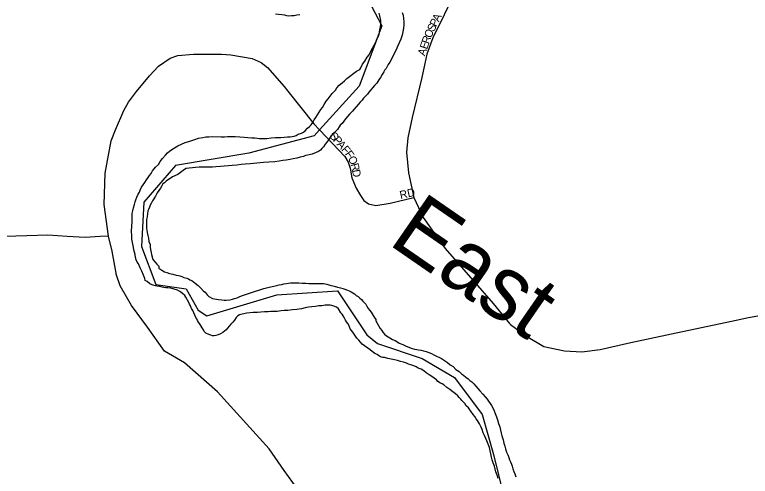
# Model space of a CAD drawing. Extents: x -561 to 1170, y 0 to 846.
# Drawn here: x 98.65 to 111.07, y 180.55 to 188.34 of the extents above; entities that cross this region are included whole.
import ezdxf

# ---------------------------------------------------------------- set-up
doc = ezdxf.new("R2010")
doc.units = 0
for name, color, linetype in [('GM_X_City_Street', 7, 'Continuous'), ('GM_X_City_Street_Text', 7, 'Continuous'), ('GM_X_County_Road', 7, 'Continuous'), ('GM_X_Major_River', 7, 'Continuous'), ('GM_X_Major_River_Text', 7, 'Continuous'), ('GM_X_Township', 7, 'Continuous')]:
    doc.layers.add(name, color=color, linetype=linetype)

msp = doc.modelspace()

# ---------------------------------------------------------------- linework, layer by layer
at = {"layer": 'GM_X_City_Street'}
for points in [[(106.097, 188.748), (105.711, 187.954), (105.606, 187.677), (105.524, 187.28), (105.36, 186.607), (105.285, 186.263), (105.262, 186.024), (105.3, 185.672), (105.387, 185.256), (105.547, 184.919), (105.916, 184.398), (106.384, 183.864), (106.727, 183.468), (107.002, 183.131)], [(103.909, 186.282), (103.921, 186.269), (104.223, 185.951), (104.278, 185.853), (104.316, 185.751), (104.341, 185.59), (104.414, 185.416), (104.486, 185.293), (104.545, 185.208), (104.626, 185.148), (104.745, 185.123), (104.991, 185.161), (105.387, 185.256)], [(107.002, 183.131), (107.017, 183.112), (107.287, 182.914), (107.584, 182.743), (107.933, 182.67), (108.223, 182.65), (108.533, 182.69), (109.047, 182.809), (109.734, 182.954), (110.749, 183.17), (111.035, 183.23), (111.351, 183.288)]]:
    msp.add_lwpolyline(points, dxfattribs=at)
at = {"layer": 'GM_X_County_Road'}
for points in [[(100.237, 184.604), (100.161, 185.137), (100.18, 185.669), (100.283, 186.213), (100.356, 186.401), (100.495, 186.727), (100.573, 186.866), (100.708, 187.049), (100.928, 187.309), (101.08, 187.476), (101.279, 187.609), (101.406, 187.654), (101.669, 187.675), (102.144, 187.678), (102.298, 187.666), (102.66, 187.606), (102.812, 187.533), (102.92, 187.454), (103.202, 187.129), (103.263, 187.051)], [(103.263, 187.051), (103.7, 186.503), (103.799, 186.398), (103.909, 186.282)], [(103.421, 180.343), (103.201, 180.649), (102.948, 181.016), (102.076, 181.979), (101.519, 182.465), (101.181, 182.664), (100.893, 183.07), (100.627, 183.433), (100.433, 183.763), (100.368, 183.962), (100.365, 183.98), (100.297, 184.349), (100.237, 184.604), (100.098, 184.6), (99.844, 184.584), (99.541, 184.6), (99.211, 184.62), (98.861, 184.612), (97.37, 184.564), (96.936, 184.564), (96.144, 184.537)]]:
    msp.add_lwpolyline(points, dxfattribs=at)
at = {"layer": 'GM_X_Major_River'}
for points in [[(105.193, 188.381), (105.209, 188.332), (105.215, 188.278), (105.22, 188.224), (105.221, 188.169), (105.215, 188.115), (105.205, 188.056), (105.189, 187.996), (105.167, 187.931), (105.14, 187.866), (105.113, 187.806), (105.092, 187.752), (105.049, 187.676), (105.017, 187.605), (104.984, 187.54), (104.957, 187.502), (104.936, 187.47), (104.92, 187.437), (104.898, 187.41), (104.882, 187.377), (104.855, 187.334), (104.828, 187.285), (104.796, 187.242), (104.763, 187.187), (104.726, 187.149), (104.628, 187.035), (104.607, 187.003), (104.575, 186.965), (104.542, 186.932), (104.515, 186.899), (104.483, 186.867), (104.45, 186.829), (104.413, 186.785), (104.375, 186.742), (104.353, 186.715), (104.305, 186.666), (104.267, 186.622), (104.235, 186.584), (104.208, 186.546), (104.181, 186.508), (104.148, 186.476), (104.127, 186.449), (104.1, 186.405), (104.051, 186.356), (104.013, 186.318), (103.981, 186.28), (103.949, 186.231), (103.922, 186.193), (103.895, 186.155), (103.862, 186.112), (103.835, 186.085), (103.814, 186.057), (103.781, 186.036), (103.673, 185.987), (103.597, 185.97), (103.559, 185.965), (103.527, 185.948), (103.473, 185.937), (103.413, 185.921), (103.354, 185.91), (103.3, 185.899), (103.235, 185.888), (103.18, 185.882), (103.115, 185.871), (103.045, 185.86), (102.942, 185.854), (102.85, 185.849), (102.742, 185.837), (102.628, 185.826), (102.541, 185.82), (102.476, 185.815), (102.401, 185.804), (102.325, 185.798), (102.26, 185.792), (102.189, 185.787), (102.124, 185.781), (102.048, 185.776), (101.994, 185.77), (101.924, 185.77), (101.843, 185.77), (101.767, 185.769), (101.707, 185.764), (101.653, 185.758), (101.599, 185.752), (101.545, 185.747), (101.518, 185.731), (101.404, 185.643), (101.318, 185.605), (101.21, 185.535), (101.183, 185.507), (101.156, 185.486), (101.139, 185.453)], [(103.465, 188.343), (103.416, 188.332), (103.367, 188.326), (103.324, 188.321), (103.28, 188.32), (103.243, 188.326), (103.21, 188.336), (103.053, 188.352)], [(103.709, 186.566), (103.736, 186.61), (103.763, 186.653), (103.79, 186.697), (103.822, 186.74), (103.849, 186.778), (103.876, 186.827), (103.908, 186.881), (103.941, 186.925), (103.979, 186.968), (104.011, 187.012), (104.038, 187.039), (104.065, 187.071), (104.092, 187.109), (104.13, 187.153), (104.178, 187.191), (104.216, 187.229), (104.259, 187.267), (104.421, 187.392), (104.475, 187.419), (104.492, 187.447), (104.524, 187.506), (104.562, 187.561), (104.599, 187.626), (104.632, 187.664), (104.664, 187.729), (104.691, 187.778), (104.718, 187.827), (104.739, 187.87), (104.761, 187.913), (104.777, 187.951), (104.793, 187.979), (104.804, 188.016), (104.809, 188.049), (104.815, 188.087), (104.825, 188.136), (104.83, 188.184), (104.83, 188.217), (104.83, 188.25), (104.819, 188.293), (104.814, 188.325), (104.803, 188.369)], [(101.286, 183.725), (101.237, 183.73), (101.205, 183.73), (101.172, 183.736), (101.14, 183.741), (101.102, 183.752), (101.053, 183.762), (101.01, 183.773), (100.972, 183.784), (100.934, 183.8), (100.89, 183.838), (100.858, 183.854), (100.847, 183.892), (100.825, 183.946), (100.798, 184.011), (100.77, 184.07), (100.743, 184.135), (100.721, 184.168), (100.705, 184.206), (100.694, 184.243), (100.688, 184.292), (100.666, 184.373), (100.655, 184.449), (100.644, 184.498), (100.633, 184.552), (100.628, 184.612), (100.627, 184.687), (100.632, 184.774), (100.638, 184.845), (100.637, 184.931), (100.637, 184.986), (100.648, 185.034), (100.658, 185.083), (100.675, 185.137), (100.685, 185.181), (100.696, 185.219), (100.712, 185.262), (100.739, 185.311), (100.76, 185.349), (100.771, 185.381), (100.793, 185.43), (100.82, 185.468), (100.852, 185.512), (100.879, 185.555), (100.906, 185.593), (100.927, 185.626), (100.954, 185.664), (100.981, 185.707), (101.03, 185.767), (101.079, 185.816), (101.111, 185.865), (101.149, 185.914), (101.197, 185.973), (101.235, 186.011), (101.267, 186.039), (101.305, 186.066), (101.348, 186.098), (101.408, 186.131), (101.467, 186.158), (101.532, 186.186), (101.592, 186.202), (101.641, 186.219), (101.695, 186.235), (101.754, 186.257), (101.83, 186.268), (101.879, 186.279), (101.928, 186.279), (101.987, 186.285), (102.139, 186.28), (102.193, 186.28), (102.242, 186.285), (102.301, 186.286), (102.372, 186.286), (102.453, 186.281), (102.524, 186.276), (102.589, 186.27), (102.654, 186.265), (102.708, 186.265), (102.746, 186.26), (102.784, 186.255), (102.827, 186.255), (102.859, 186.255), (102.908, 186.255), (102.979, 186.266), (103.055, 186.272), (103.147, 186.272), (103.201, 186.278), (103.255, 186.283), (103.304, 186.283), (103.336, 186.289), (103.369, 186.294), (103.401, 186.305), (103.439, 186.327), (103.493, 186.344), (103.526, 186.36), (103.553, 186.382), (103.596, 186.425), (103.628, 186.458), (103.655, 186.485), (103.682, 186.523), (103.709, 186.566)], [(101.139, 185.453), (101.112, 185.415), (101.085, 185.377), (101.059, 185.334), (101.032, 185.279), (100.999, 185.236), (100.978, 185.198), (100.962, 185.165), (100.94, 185.127), (100.929, 185.095), (100.913, 185.057), (100.902, 185.03), (100.892, 184.986), (100.887, 184.932), (100.876, 184.883), (100.876, 184.829), (100.876, 184.775), (100.876, 184.742), (100.882, 184.705), (100.887, 184.667), (100.898, 184.618), (100.909, 184.569), (100.92, 184.515), (100.937, 184.461), (100.942, 184.418), (100.948, 184.38), (100.954, 184.331), (100.965, 184.293), (100.986, 184.212), (101.025, 184.163), (101.052, 184.131), (101.084, 184.098), (101.085, 184.066), (101.139, 184.028), (101.182, 184.001), (101.22, 183.99), (101.264, 183.974), (101.323, 183.964), (101.378, 183.948), (101.415, 183.942), (101.443, 183.932), (101.475, 183.921), (101.508, 183.905), (101.556, 183.894), (101.584, 183.883), (101.611, 183.867), (101.643, 183.856), (101.698, 183.813), (101.752, 183.77), (101.795, 183.727), (101.839, 183.678), (101.866, 183.657), (101.899, 183.613), (101.931, 183.586), (101.991, 183.554), (102.094, 183.533), (102.148, 183.527), (102.186, 183.522), (102.224, 183.522), (102.284, 183.528), (102.327, 183.539), (102.365, 183.55), (102.408, 183.566), (102.452, 183.583), (102.495, 183.604), (102.565, 183.626), (102.63, 183.648), (102.857, 183.719), (102.949, 183.741), (103.025, 183.758), (103.079, 183.769), (103.117, 183.78), (103.161, 183.791), (103.193, 183.802), (103.242, 183.807), (103.307, 183.818), (103.377, 183.818), (103.448, 183.819), (103.507, 183.813), (103.567, 183.808), (103.616, 183.803), (103.654, 183.803), (103.697, 183.803), (103.74, 183.803), (103.767, 183.803), (103.794, 183.804), (103.865, 183.804), (103.919, 183.793), (103.973, 183.777), (104.044, 183.761), (104.103, 183.745), (104.152, 183.734), (104.19, 183.718), (104.223, 183.707), (104.272, 183.691), (104.299, 183.68), (104.331, 183.664), (104.358, 183.648), (104.386, 183.632), (104.418, 183.605), (104.451, 183.583)], [(105.213, 182.475), (105.164, 182.491), (105.115, 182.507), (105.061, 182.518), (105.007, 182.529), (104.947, 182.539), (104.893, 182.555), (104.866, 182.555), (104.828, 182.566), (104.795, 182.588), (104.768, 182.604), (104.741, 182.62), (104.714, 182.636), (104.654, 182.685), (104.518, 182.782), (104.486, 182.814), (104.459, 182.847), (104.426, 182.884), (104.393, 182.933), (104.361, 182.982), (104.317, 183.041), (104.295, 183.09), (104.273, 183.128), (104.252, 183.16), (104.235, 183.187), (104.219, 183.22), (104.197, 183.258), (104.181, 183.285), (104.159, 183.312), (104.115, 183.377), (104.083, 183.403), (104.039, 183.425), (104.007, 183.436), (103.974, 183.441), (103.942, 183.441), (103.893, 183.441), (103.834, 183.43), (103.785, 183.43), (103.731, 183.419), (103.666, 183.413), (103.612, 183.407), (103.557, 183.396), (103.492, 183.38), (103.417, 183.369), (103.341, 183.358), (103.265, 183.352), (103.2, 183.347), (103.151, 183.341), (103.081, 183.335), (103.027, 183.33), (102.973, 183.33), (102.929, 183.329), (102.87, 183.329), (102.805, 183.324), (102.75, 183.318), (102.718, 183.318), (102.68, 183.318), (102.572, 183.307), (102.49, 183.29), (102.447, 183.274), (102.42, 183.257), (102.393, 183.23), (102.361, 183.187), (102.334, 183.154), (102.301, 183.116), (102.274, 183.084), (102.247, 183.051), (102.22, 183.024), (102.193, 183.002), (102.166, 182.98), (102.129, 182.953), (102.085, 182.937), (102.047, 182.926), (102.02, 182.92), (101.993, 182.92), (101.966, 182.931), (101.928, 182.942), (101.879, 182.969), (101.852, 182.996), (101.841, 183.023), (101.819, 183.055), (101.803, 183.087), (101.781, 183.115), (101.754, 183.152), (101.738, 183.179), (101.727, 183.206), (101.71, 183.233), (101.694, 183.271), (101.678, 183.309), (101.661, 183.347), (101.639, 183.385), (101.618, 183.428), (101.601, 183.455), (101.59, 183.482), (101.541, 183.574), (101.525, 183.601), (101.487, 183.639), (101.443, 183.671), (101.4, 183.693), (101.346, 183.709), (101.286, 183.725)], [(104.451, 183.583), (104.478, 183.556), (104.505, 183.535), (104.527, 183.508), (104.554, 183.481), (104.576, 183.454), (104.598, 183.421), (104.619, 183.384), (104.647, 183.351), (104.668, 183.319), (104.685, 183.292), (104.701, 183.265), (104.717, 183.238), (104.745, 183.2), (104.75, 183.173), (104.799, 183.086), (104.821, 183.048), (104.848, 183.01), (104.865, 182.983), (104.892, 182.951), (104.93, 182.919), (104.984, 182.886), (105.028, 182.859), (105.071, 182.843), (105.103, 182.827), (105.141, 182.8), (105.201, 182.773), (105.25, 182.752), (105.315, 182.725), (105.358, 182.709), (105.402, 182.698), (105.44, 182.693), (105.467, 182.687), (105.51, 182.682), (105.554, 182.666), (105.597, 182.655), (105.64, 182.639), (105.684, 182.623), (105.727, 182.601), (105.771, 182.58), (105.82, 182.558), (105.858, 182.537), (105.906, 182.504), (105.955, 182.472), (106.004, 182.434), (106.053, 182.402), (106.097, 182.353), (106.151, 182.321), (106.194, 182.283), (106.227, 182.256), (106.265, 182.224), (106.303, 182.197), (106.336, 182.17), (106.368, 182.143), (106.401, 182.11), (106.433, 182.073), (106.466, 182.035), (106.504, 181.992), (106.553, 181.938), (106.591, 181.894), (106.624, 181.851), (106.7, 181.743), (106.722, 181.705), (106.744, 181.656), (106.76, 181.608), (106.782, 181.554), (106.798, 181.505), (106.815, 181.44), (106.837, 181.386), (106.848, 181.332), (106.864, 181.278), (106.875, 181.234), (106.886, 181.202), (106.897, 181.164), (106.908, 181.11), (106.924, 181.061), (106.936, 181.012), (106.952, 180.958), (106.974, 180.915), (106.99, 180.866), (107.001, 180.828), (107.018, 180.796), (107.034, 180.758), (107.045, 180.72), (107.061, 180.677), (107.078, 180.634), (107.094, 180.59), (107.111, 180.542)], [(106.813, 180.514), (106.796, 180.568), (106.774, 180.627), (106.752, 180.719), (106.725, 180.779), (106.709, 180.827), (106.698, 180.876), (106.687, 180.93), (106.676, 180.979), (106.665, 181.039), (106.643, 181.093), (106.621, 181.147), (106.604, 181.19), (106.583, 181.239), (106.561, 181.287), (106.539, 181.342), (106.522, 181.379), (106.506, 181.412), (106.495, 181.439), (106.463, 181.493), (106.441, 181.52), (106.419, 181.558), (106.392, 181.596), (106.31, 181.709), (106.272, 181.742), (106.25, 181.78), (106.201, 181.828), (106.18, 181.855), (106.152, 181.882), (106.131, 181.909), (106.093, 181.942), (106.049, 181.974), (105.995, 182.017), (105.946, 182.049), (105.892, 182.093), (105.864, 182.109), (105.837, 182.125), (105.794, 182.152), (105.772, 182.179), (105.734, 182.206), (105.691, 182.233), (105.647, 182.265), (105.598, 182.298), (105.555, 182.33), (105.511, 182.357), (105.463, 182.378), (105.425, 182.4), (105.387, 182.416), (105.338, 182.432), (105.3, 182.443), (105.262, 182.459), (105.213, 182.475)]]:
    msp.add_lwpolyline(points, dxfattribs=at)
at = {"layer": 'GM_X_Township'}
msp.add_lwpolyline([(104.49, 188.848), (104.847, 188.155), (104.467, 187.137), (103.799, 186.398), (103.708, 186.297), (102.604, 186.005), (101.369, 185.795), (100.832, 185.177), (100.794, 184.43), (101.037, 183.791), (101.546, 183.715), (101.751, 183.357), (101.897, 183.259), (103.078, 183.616), (104.102, 183.682), (104.593, 182.938), (104.777, 182.792), (105.529, 182.537), (106.076, 182.217), (106.541, 181.594), (106.735, 180.917), (106.988, 179.888)], dxfattribs=at)

# ---------------------------------------------------------------- texts
at = {"layer": 'GM_X_City_Street_Text'}
for s, rotation, p in [('P', 63.4472, (105.767, 188.129)), ('A', 63.4349, (105.809, 188.214)), ('S', 63.5327, (105.725, 188.044)), ('O', 65.6935, (105.676, 187.937)), ('R', 70.797, (105.642, 187.839)), ('E', 71.4527, (105.612, 187.749)), ('A', 71.4752, (105.574, 187.637)), ('S', 311.4044, (103.954, 186.291)), ('P', 311.3941, (104.017, 186.22)), ('A', 311.4005, (104.08, 186.149)), ('F', 311.3962, (104.158, 186.06)), ('F', 305.9792, (104.219, 185.991)), ('O', 295.1866, (104.272, 185.92)), ('R', 283.9302, (104.32, 185.819)), ('D', 280.6412, (104.345, 185.717)), ('RD', 12.5224, (105.165, 185.23))]:
    msp.add_text(s, height=0.135, rotation=rotation, dxfattribs=at).set_placement(p)
at = {"layer": 'GM_X_Major_River_Text'}
msp.add_text('East', height=1.0806, rotation=325.3782, dxfattribs=at).set_placement((104.935, 184.483))

doc.saveas('drawing.dxf')
